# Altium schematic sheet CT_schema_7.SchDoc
size 254 x 245 mm
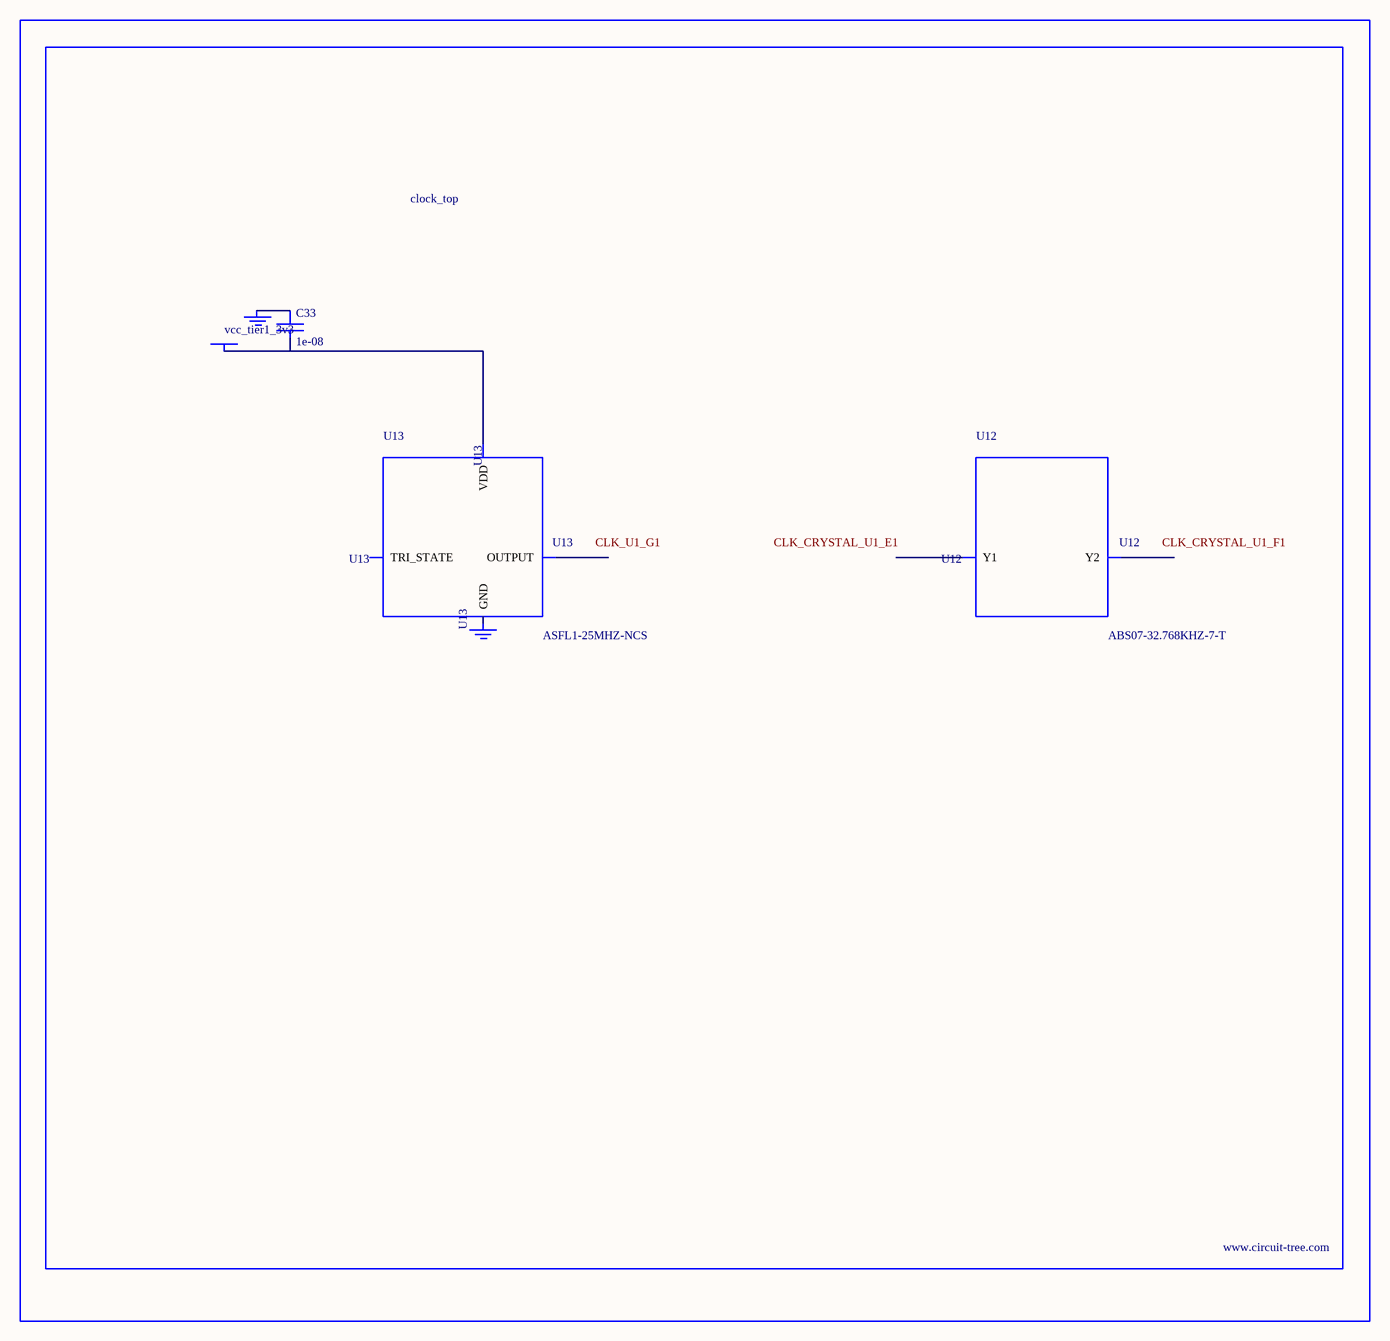
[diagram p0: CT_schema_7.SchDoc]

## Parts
BORDER6  (no value)
C33  1e-08  [C0402]
GND_INSTANCE_6_0  (no value)
GND_INSTANCE_6_1  (no value)
POWER_INSTANCE_6_0  vcc_tier1_3v3
U12  ABS07-32.768KHZ-7-T  [ABS07-32.768KHZ-7-T]
U13  ASFL1-25MHZ-NCS  [ASFL1]

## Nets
NetC33_1: C33.1 GND_INSTANCE_6_0.0(GND)
NetC33_2: C33.2 POWER_INSTANCE_6_0.0(PWR) U13.4(VDD)

Not connected (* = marked no-connect by the designer): GND_INSTANCE_6_1 0(GND); U12 1(Y1) 2(Y2); U13 1(TRI_STATE) 2(GND) 3(OUTPUT)

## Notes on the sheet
- Labels drawn without touching a wire or pin: CLK_CRYSTAL_U1_E1, CLK_CRYSTAL_U1_F1, CLK_U1_G1

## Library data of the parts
BORDER6 = BORDER_PAGE6
C33 = C0402C103K3RAC
GND_INSTANCE_6_0 GND_INSTANCE_6_1 = GND
POWER_INSTANCE_6_0 = PWR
